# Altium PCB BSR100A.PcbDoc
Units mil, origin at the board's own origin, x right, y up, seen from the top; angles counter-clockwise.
Board outline 2168.5 x 1988.5 mil, 2 copper layers (Top Layer, Bottom Layer), stack 61.2 mil thick; 46 components, 9 nets, 68 pads, 112 vias.
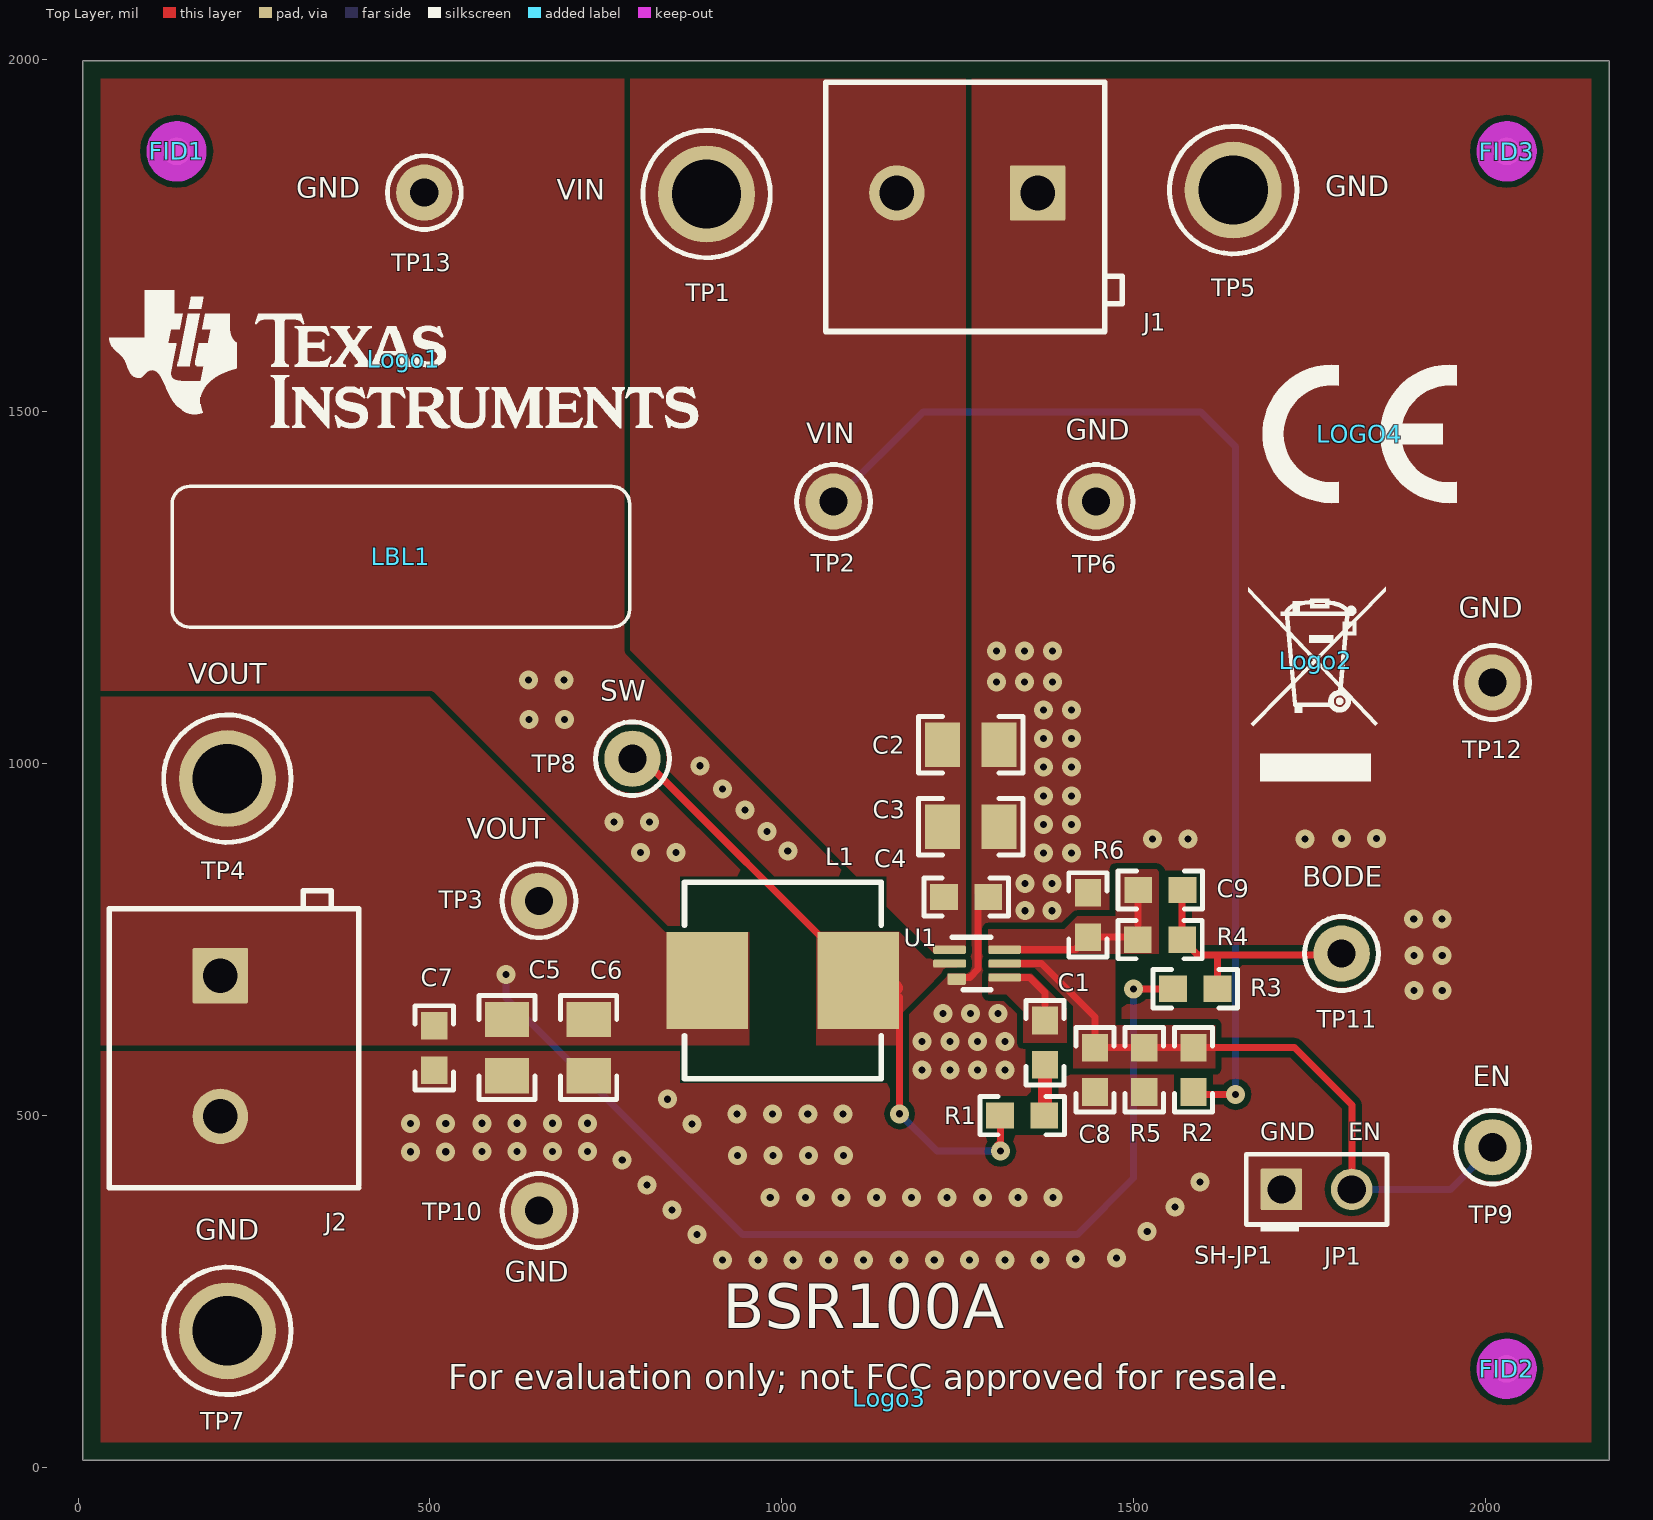
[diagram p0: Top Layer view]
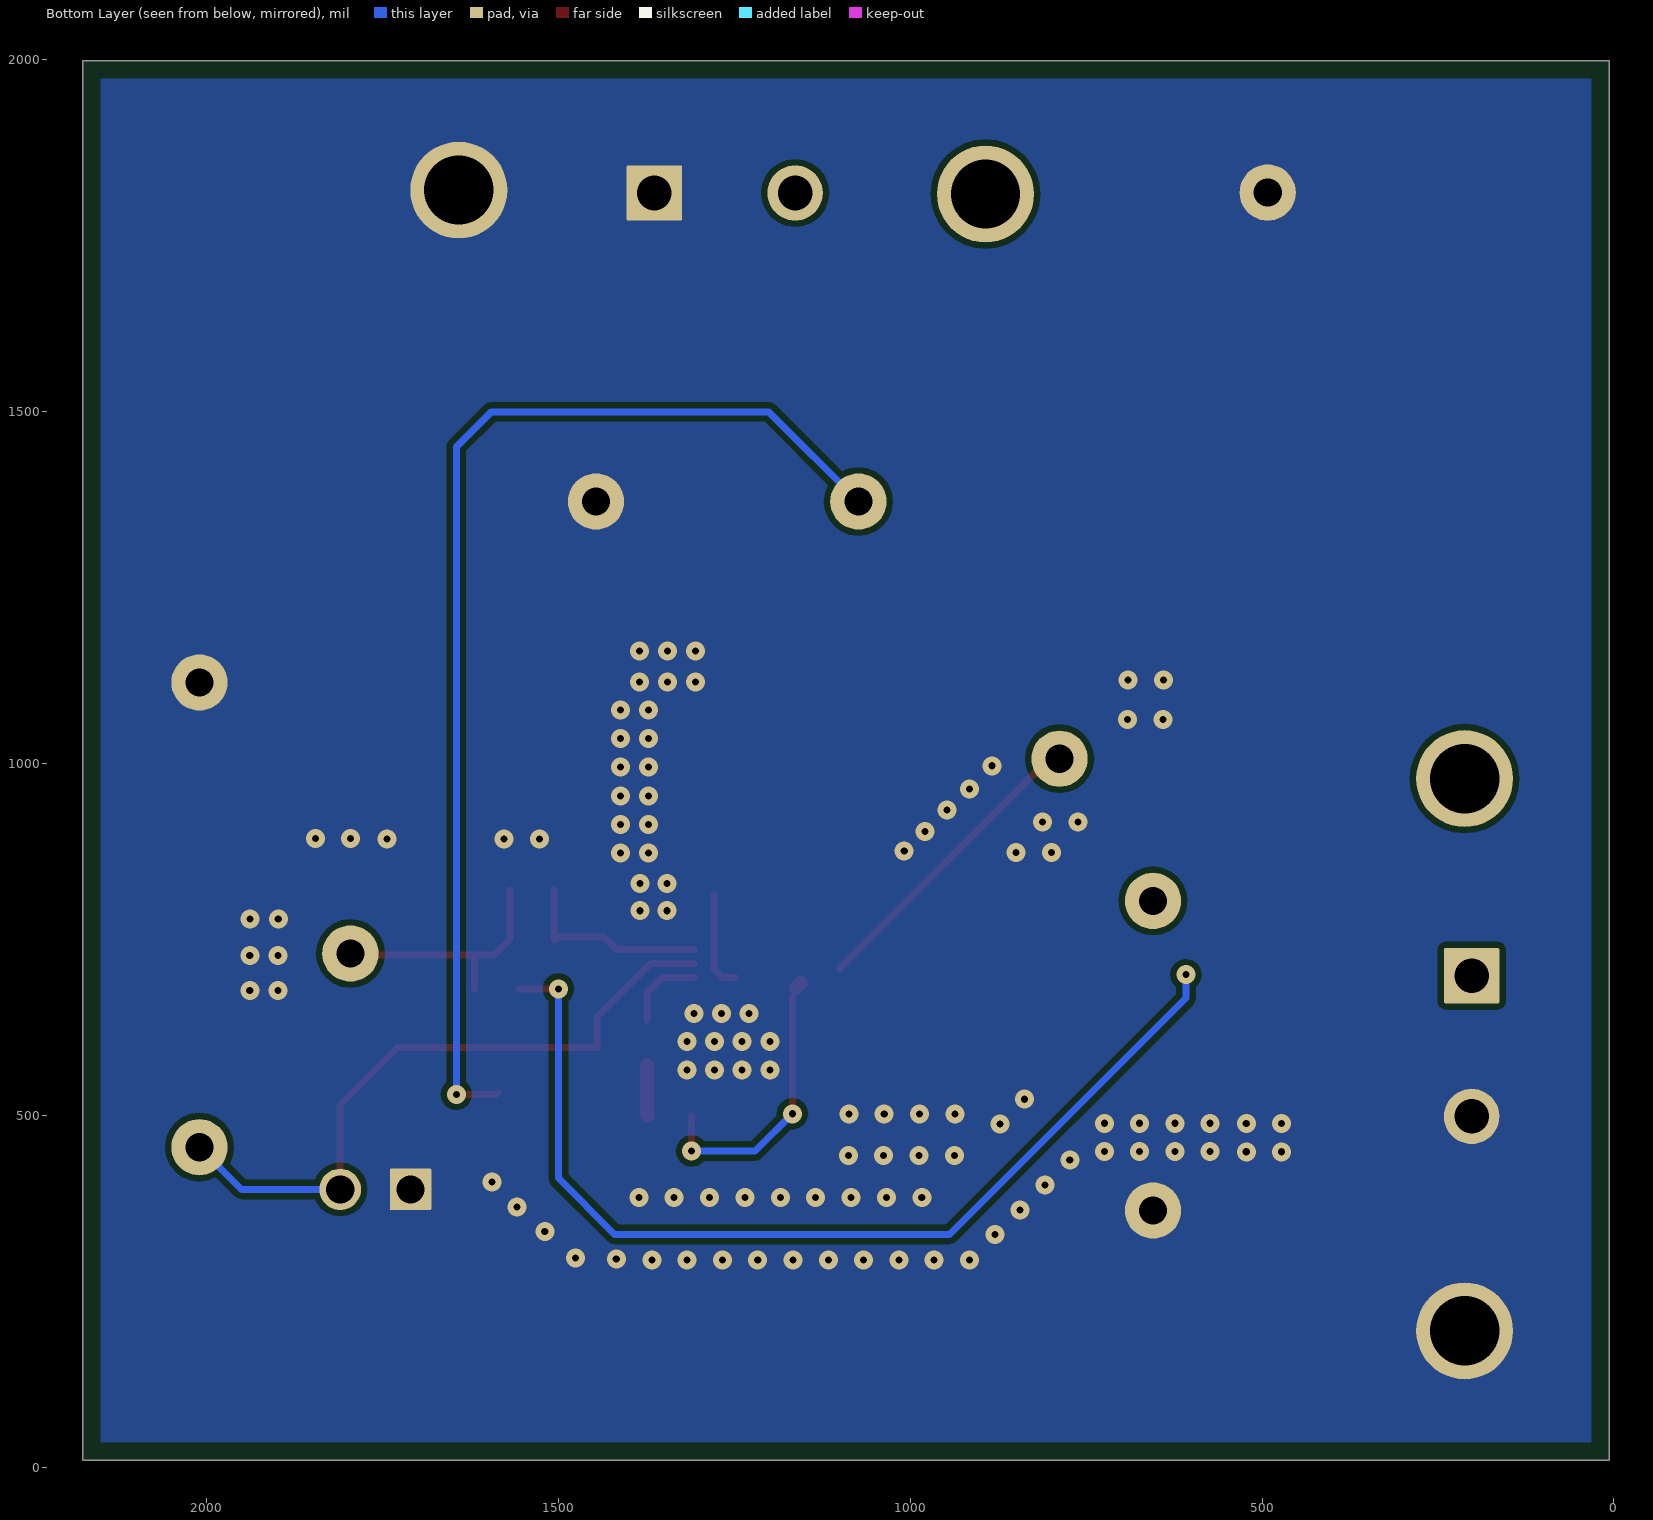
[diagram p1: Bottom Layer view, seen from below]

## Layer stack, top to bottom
Top Solder: solder mask 0.4, Solder Resist, Dk 3.5
Top Layer: signal copper 2.8
Dielectric1: core 55.6, FR-4 High Tg, Dk 4.8
Bottom Layer: signal copper 2.8
Bottom Solder: solder mask 0.4, Solder Resist, Dk 3.5

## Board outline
7,10 2175.5,10 2175.5,1998.5 7,1998.5

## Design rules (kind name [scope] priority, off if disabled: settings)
AcuteAngle [All] p1: minimum=4.50000000000000E+0001 checktracksonly=FALSE
AssemblyTestPointUsage [All] p1: valid=2
BoardOutlineClearance BoardOutlineClearance_MountingHoles [OnCopper and InComponentClass('Mounting Holes')] p1: gap=40 ignorepadtopadclearanceinfootprint=FALSE
BoardOutlineClearance BoardOutlineClearance_Poly [OnCopper and IsPoly] p2: gap=25 ignorepadtopadclearanceinfootprint=FALSE
BoardOutlineClearance [OnCopper and Not InComponentClass('Logo') and not InComponentClass('FiducialMark') and not InRegion(1000,500,4000,800) and not InPoly] p3: gap=75 ignorepadtopadclearanceinfootprint=FALSE
Clearance Clearance_Keepouts [((IsTrack Or IsArc) And Not InPoly) And IsFree and IsKeepOut vs ((IsTrack Or IsArc) And Not InPoly) And IsFree and IsKeepOut] p1: gap=0 ignorepadtopadclearanceinfootprint=FALSE
Clearance Clearance_Poly [InPolygon] p2: gap=8.5 ignorepadtopadclearanceinfootprint=FALSE except(0: Arc-Hole Track-Hole SMDPad-Hole THPad-Hole Via-Hole Fill-Hole Poly-Hole Region-Hole Text-Hole)
Clearance [All] p3: gap=7 ignorepadtopadclearanceinfootprint=FALSE except(0: Arc-Hole Track-Hole SMDPad-Hole THPad-Hole Via-Hole Fill-Hole Poly-Hole Region-Hole Text-Hole)
ComponentClearance ComponentClearance_MountingHoles_FiducialMarks [InComponentClass('Mounting Holes') vs InComponentClass('FiducialMark')] p1: gap=50 collisioncheckmode=3 verticalgap=10 showdistances=FALSE
ComponentClearance ComponentClearance_Shunt [InComponentClass('Header') vs InComponentClass('Shunt')] p2: gap=0 collisioncheckmode=3 verticalgap=0 showdistances=FALSE
ComponentClearance ComponentClearance_Logo [InComponentClass('Logo')] p3: gap=50 collisioncheckmode=3 verticalgap=10 showdistances=FALSE
ComponentClearance ComponentClearance_ScrewToNut [(HasFootprint('NY PMS 440 0025 PH')) vs (HasFootprint('Keystone_1902C'))] p4: gap=5 collisioncheckmode=3 verticalgap=10 showdistances=FALSE
ComponentClearance ComponentClearance_MountingHoles [InComponentClass('Mounting Holes')] p5: gap=250 collisioncheckmode=3 verticalgap=100000 showdistances=FALSE
ComponentClearance ComponentClearance_SmallPassives [HasFootprint('0201*') or HasFootprint('0402*') or HasFootprint('0508') or HasFootprint('0603*') or HasFootprint('0612') or HasFootprint('0805*') or HasFootprint('0815*') or HasFootprint('0830*') or HasFootprint('1206*') or HasFootprint('1210*') or HasFootprint('1808*') or HasFootprint('1812*') or HasFootprint('1825*') or HasFootprint('2010*') or HasFootprint('2220*') or HasFootprint('2225*') or HasFootprint('2512*') or HasFootprint('2728*') or HasFootprint('3518*') vs HasFootprint('0201*') or HasFootprint('0402*') or HasFootprint('0508') or HasFootprint('0603*') or HasFootprint('0612') or HasFootprint('0805*') or HasFootprint('0815*') or HasFootprint('0830*') or HasFootprint('1206*') or HasFootprint('1210*') or HasFootprint('1808*') or HasFootprint('1812*') or HasFootprint('1825*') or HasFootprint('2010*') or HasFootprint('2220*') or HasFootprint('2225*') or HasFootprint('2512*') or HasFootprint('2728*') or HasFootprint('3518*')] p6: gap=14.96 collisioncheckmode=3 verticalgap=10 showdistances=FALSE
ComponentClearance ComponentClearance_THtoSMT [IsThruComponent vs IsSMTComponent] p7: gap=40 collisioncheckmode=3 verticalgap=30 showdistances=FALSE
ComponentClearance ComponentClearance_THtoTH [IsThruComponent vs IsThruComponent] p8: gap=30 collisioncheckmode=3 verticalgap=30 showdistances=FALSE
ComponentClearance [All] p9: gap=30 collisioncheckmode=3 verticalgap=10 showdistances=FALSE
DiffPairsRouting [All] p1: maxlimit=100 minlimit=10 mostfreqgap=10 toplayer_minwidth=15 toplayer_maxwidth=15 toplayer_prefwidth=15 bottomlayer_minwidth=15 bottomlayer_maxwidth=15 bottomlayer_prefwidth=15 maxuncoupledlength=1000
FabricationTestPointUsage TestPointUsage [All] p1: valid=2 allowmultiple=FALSE
FabricationTestpoint Testpoint [All] p1: side=3 testpointundercomponent=TRUE minsize=40 maxsize=100 preferedsize=60 minholesize=0 maxholesize=40 preferedholesize=32 testpointgrid=1 allowsidetop=TRUE allowsidebottom=TRUE usegrid=TRUE gridtolerance=0.01
FanoutControl Fanout_LCC [IsLCC] p1: bgadir=Out bgaviamode=Centered fanoutstyle=Auto fanoutdirection=Alternating viagrid=1 // Fanout_LCC (Default Rule)
FanoutControl Fanout_BGA [IsBGA] p2: bgadir=Out bgaviamode=Centered fanoutstyle=Auto fanoutdirection=Alternating viagrid=1 // Fanout_BGA (Default Rule)
FanoutControl Fanout_Default [All] p4: bgadir=Out bgaviamode=Centered fanoutstyle=Auto fanoutdirection=Alternating viagrid=1 // Fanout_Default (Default Rule)
FanoutControl Fanout_Small [(CompPinCount < 5)] p5: bgadir=Out bgaviamode=Centered fanoutstyle=Auto fanoutdirection=OutThenIn viagrid=1 // Fanout_Small (Default Rule)
HoleSize [All] p1: absolutevalues=TRUE maxlimit=251 minlimit=7.87 maxpercent=80.000 minpercent=20.000
MinimumAnnularRing MinimumAnnularRing_ThermalPadVias [IsVia and InAnyComponent] p1: minimumring=5.91
MinimumAnnularRing [All] p2: minimumring=6
MinimumSolderMaskSliver MinimumSolderMaskSliver_Logo [InComponentClass('Logo') vs InComponentClass('Logo')] p1: minsoldermaskwidth=0.7
MinimumSolderMaskSliver [All] p2: minsoldermaskwidth=3.94
PlaneClearance [All] p1: clearance=0
PlaneConnect [All] p1: planeconnectstyle=Direct reliefexpansion=10 reliefentries=2 reliefconductorwidth=10 reliefairgap=10
PolygonConnect [All] p1: connectstyle=Direct reliefconductorwidth=10 reliefentries=4 polygonreliefangle="90 Angle" airgapwidth=10
RoutingVias ThermalPadVias [IsVia and InAnyComponent] p1: holewidth=7.87 width=19.68 viastyle="Through Hole" minholewidth=7.87 minwidth=19.68 maxholewidth=12.99 maxwidth=23.62
RoutingVias [All] p2: holewidth=16 width=34 viastyle="Through Hole" minholewidth=7.87 minwidth=26 maxholewidth=40 maxwidth=65
SilkToBoardRegionClearance [Not ((IsComment or IsDesignator) And (Hide <> 'False')) and not InRegion(1000,500,4000,800)] p1:
SilkToSilkClearance SilkToSilkClearance_Pb-FreeLogo [(HasFootprint('Pb-Free_Overlay_Medium') OR HasFootprint('Pb-Free_Overlay_Small')) vs (HasFootprint('Pb-Free_Overlay_Medium') OR HasFootprint('Pb-Free_Overlay_Small'))] p1: silktosilkclearance=0
SilkToSilkClearance [All] p2: silktosilkclearance=4
SilkToSolderMaskClearance SilkToComponentPadClearance [(IsPad or IsFill or IsRegion) and InAnycomponent] p1: minsilkscreentomaskgap=2 clearancetoexposedcopper=TRUE
SilkToSolderMaskClearance "Silk to Solder Mask Opening" [All] p2: minsilkscreentomaskgap=0.5 clearancetoexposedcopper=TRUE
SolderMaskExpansion [All] p1: expansion=1.85
Width [All] p1: maxlimit=100 minlimit=3 preferedwidth=10 bottomlayer_minwidth=6 minimp=50.000000 maximp=50.000000 favimp=50.000000 checkconnectedcopper=TRUE
14 further rules are at their usual default settings.

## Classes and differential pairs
component class Label: LBL1
component class Shunt: SH-JP1
component class FiducialMark: FID1 FID2 FID3
component class BSR100A_Hardware: FID1 FID2 FID3 LBL1 Logo1 Logo2 Logo3 LOGO4 LOGO7 SH-JP1 ZZ1 ZZ2 ZZ3 ZZ4
component class Logo: Logo1
component class Header: JP1
component class BSR100A: C1 C2 C3 C4 C5 C6 C7 C8 C9 GND GND3 J1 J2 JP1 L1 R1 R2 R3 R4 R5 R6 TP1 TP2 TP3 TP4 TP5 TP6 TP7 TP8 TP9 TP10 TP11 TP12 TP13 U1 VIN1 VOUT0
component class AssemblyNote: ZZ1 ZZ2 ZZ3 ZZ4

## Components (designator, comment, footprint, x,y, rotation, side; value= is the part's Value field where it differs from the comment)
C1 "C1608X7R1E104K080AA" 0603 1374,603.5 r270 top value=0.1uF
C2 "GRM21BR61E106MA73L" 0805_HV 1268.5,1027 r0 top value=10uF
C3 "GRM21BR61E106MA73L" 0805_HV 1268.5,910.5 r0 top value=10uF
C4 "C1608X7R1E104K080AA" 0603 1262,810.5 r0 top value=0.1uF
C5 "GRM21BR61A226ME44L" 0805_HV 609.5,596.5 r90 top value=22uF
C6 "GRM21BR61A226ME44L" 0805_HV 725.5,596.5 r90 top value=22uF
C7 "C1608X7R1E104K080AA" 0603 506,596 r270 top value=0.1uF
C8 "C1608X7R1H103K080AA" 0603 1445,565 r270 top value=0.01uF
C9 "GRM1885C2A330JA01D" 0603 1538,820.5 r180 top value=33pF
FID1 "Fiducial" Fiducial10-20 140,1870 r0 top
FID2 "Fiducial" Fiducial10-20 2030,140 r0 top
FID3 "Fiducial" Fiducial10-20 2030,1870 r0 top
J1 "ED120/2DS" On-Shore_ED120_2DS 1263.55,1810.91 r180 top
J2 "ED120/2DS" On-Shore_ED120_2DS 202.15,598.71 r270 top
JP1 "PEC02SAAN" CONN_PEC02SAAN 1760,395 r0 top
L1 "74437349012" WE-LHMI_7050 1001.5,692 r180 top value=1.2uH
LBL1 "THT-14-423-10" Label_650x200 458.68,1294 r0 top
Logo1 "Texas Instruments" TI_Stacked_Overlay_Small 463,1574.5 r0 top
Logo2 "WEEE logo" WEEE_Minimum 1758.5,1147 r0 top
Logo3 "FCC disclaimer" FCC_disclaimer 1153,99 r0 top
LOGO4 "CE Mark" CE_Mark_5mm 1821,1468.5 r0 top
R1 "CRCW06030000Z0EA" 0603 1341.5,500 r180 top value=0
R2 "CRCW060320K0JNEA" 0603 1585,565 r270 top value=20k
R3 "CRCW060351R0JNEA" 0603 1587.5,680 r180 top value=51
R4 "RC0603FR-073K09L" 0603 1537.5,750 r180 top value=3.09k
R5 "CRCW060310K0JNEA" 0603 1515,565 r90 top value=10k
R6 "CRCW060310K0FKEA" 0603 1435,785 r270 top value=10.0k
SH-JP1 "SNT-100-BK-G" SNT-100-BK-G 1656,400.5 r180 top value=1x2
TP1 "1502-2" Keystone1502-2 893.05,1809.41 r0 top
TP2 "5000" Keystone5000 1073.64,1372.46 r90 top
TP3 "5000" Keystone5000 655,805 r0 top
TP4 "1502-2" Keystone1502-2 212.15,978.71 r0 top
TP5 "1502-2" Keystone1502-2 1641.5,1815 r0 top
TP6 "5001" Keystone5001 1446.5,1372.46 r90 top
TP7 "1502-2" Keystone1502-2 212.15,194 r0 top
TP8 "5000" Keystone5000 787.75,1007 r90 top
TP9 "5000" Keystone5000 2010,455 r0 top
TP10 "5001" Keystone5001 655,365 r0 top
TP11 "5000" Keystone5000 1795.5,730.2 r0 top
TP12 "5001" Keystone5001 2010,1115.32 r0 top
TP13 "5001" Keystone5001 492,1811.5 r90 top
U1 "TPS563202DRLR" DRL0006A 1277.55,715.91 r0 top
ZZ1 "This Assembly Note is for PCB labels only" AssemblyNoteLabel 3692.5,766.5 r0 top
ZZ2 "These assemblies are ESD sensitive, ESD precautions shall be observed." AssemblyNote 3694.5,622 r0 top
ZZ3 "These assemblies must be clean and free from flux and all contaminants. Use of no clean flux is not acceptable." AssemblyNote 3694.5,498.5 r0 top
ZZ4 "These assemblies must comply with workmanship standards IPC-A-610 Class 2., unless otherwise specified." AssemblyNote 3694.5,366 r0 top

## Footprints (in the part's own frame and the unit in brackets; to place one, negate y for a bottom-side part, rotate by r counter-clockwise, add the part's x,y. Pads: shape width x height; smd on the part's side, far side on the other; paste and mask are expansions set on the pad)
0603 [mm] "0603 from SM-752 data"
  rect 1x0.95 smd: 1(-0.8,0) 2(0.8,0)
  silkscreen extent -1.52,-0.69 1.52,0.69, body extent -0.87,-0.47 0.87,0.47, height 1
0805_HV [mil] "0805 with 30mil clearance between pads"
  rect 50x63 smd: 1(-40,0) 2(40,0)
  silkscreen extent -74,-40 74,40, body extent -43,-29 43,29, height 57
AssemblyNote [mil] "Assembly Note"
AssemblyNoteLabel [mil] "Assembly Note for PCB Labels"
CE_Mark_5mm [mil] "Minimum text height for CE Mark"
  silkscreen extent -138,-98 138,98
CONN_PEC02SAAN [mm] "SULLINS"
  rrect7% 1.5x1.5 hole 1.016: 1(-1.27,0)
  round 1.5 hole 1.016: 2(1.27,0)
  silkscreen extent -2.54,-1.52 2.54,1.27, body extent -2.54,-1.27 2.54,1.27, height 8.38
DRL0006A [mm] "SOTFL, 6-Flat Leads, Body 1.2x1.6x0.6mm, Pitch 0.5mm, TI recommended"
  rrect33% 0.67x0.3 smd: 1(-0.74,0.5) 2(-0.74,0) 3(-0.74,-0.5) 4(0.74,-0.5) 5(0.74,0) 6(0.74,0.5)
  silkscreen extent -0.9,-0.95 0.5,0.95, body extent -0.8,-0.8 0.8,0.8, height 0.61
FCC_disclaimer [mil]
Fiducial10-20 [mm]
  round 1 smd mask+0.5: 1(0,0)
  Top Layer keep-out circle w1.178: c0,0 r0.5
Keystone1502-2 [mm] "Double Turret"
  round 3.5 hole 2.5: 1(0,0)
  silkscreen extent -2.3,-2.3 2.3,2.3, body extent -1.6,-1.6 1.59,1.6, height 5.62
Keystone5000 [mil] "For Keystone 500x miniature loop terminals"
  round 80 hole 40: 1(0,0)
  silkscreen extent -52,-52 52,52, body extent -49,-49 49,49, height 182
Keystone5001 [mil] "For Keystone 500x miniature loop terminals"
  round 80 hole 40: 1(0,0)
  silkscreen extent -52,-52 52,52, body extent -49,-49 49,49, height 182
Label_650x200 [mil] "Thermal Transfer Label"
  round 1 on Mech13: 0(0,0)
  silkscreen extent -325,-100 325,100, body extent -325,-100 325,100, height 1
On-Shore_ED120_2DS [mm] "ONSHORE"
  rrect5% 2x2 hole 1.25: 1(-2.54,0)
  round 2 hole 1.25: 2(2.54,0)
  silkscreen extent -5.6,-4 5.12,5, body extent -5.78,-4 5.08,5, height 13
SNT-100-BK-G [mil] "Samtec STEP model"
  round 1 on Mech3: 0(0,0)
  body extent -100,-50 100,50, height 344
TI_Stacked_Overlay_Small [mil]
  silkscreen extent -418,-98 418,98
WE-LHMI_7050 [mm] "Wurth"
  rect 2.95x3.5 smd: 1(-2.725,0) 2(2.725,0)
  silkscreen extent -3.55,-3.55 3.55,3.55, body extent -3.8,-3.45 3.8,3.45, height 5
WEEE_Minimum [mil] "WEEElie bin"
  silkscreen extent -95,-172 99,104

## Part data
C1 C4 C7: library part CMP-0007039-5, "CAP, CERM, 0.1 uF, 25 V, +/- 10%, X7R, 0603", Cap_Case=0603, Manufacturer=TDK, Supplier Part Number 1=445-1316-1-ND, TempCo=X7R, Tolerance_%=10%, Value1=Unknown, Value2=25V, ValueDisplayed=0.1uF
C2 C3: library part CMP-0008303-3, "CAP, CERM, 10 uF, 25 V, +/- 20%, X5R, 0805", Cap_Case=0805, Manufacturer=MuRata, TempCo=X5R, Tolerance_%=20%, Value1=Unknown, Value2=25V, ValueDisplayed=10uF
C5 C6: library part CMP-0008286-2, "CAP, CERM, 22 uF, 10 V, +/- 20%, X5R, 0805", Cap_Case=0805, Manufacturer=MuRata, Supplier Part Number 1=490-10746-1-ND, TempCo=X5R, Tolerance_%=20%, Value1=Unknown, Value2=10V, ValueDisplayed=22uF
C8: library part CMP-0007043-4, "CAP, CERM, 0.01 uF, 50 V, +/- 10%, X7R, 0603", Cap_Case=0603, Manufacturer=TDK, Supplier Part Number 1=445-1311-1-ND, TempCo=X7R, Tolerance_%=10%, Value1="0.0539 ohm", Value2=50V, ValueDisplayed=0.01uF
C9: library part CMP-0007263-4, "CAP, CERM, 33 pF, 100 V, +/- 5%, C0G/NP0, 0603", Cap_Case=0603, Manufacturer=MuRata, Supplier Part Number 1=490-1339-1-ND, TempCo=C0G/NP0, Tolerance_%=5%, Value1=Unknown, Value2=100V, ValueDisplayed=33pF
FID1 FID2 FID3: library part CMP-0077181-1, "Fiducial mark.  There is nothing to buy or mount.", Manufacturer=N/A
J1 J2: library part CMP-0074910-1, "Terminal Block, 5.08 mm, 2x1, Brass, TH", Color=Blue, Current_A=15A, Manufacturer="On-Shore Technology", Supplier Part Number 1=ED1609-ND, Voltage_V=300V
JP1: library part CMP-0002337-1, "Header, 100mil, 2x1, Tin, TH", Color=Black, Current_A=3A, Manufacturer="Sullins Connector Solutions", Supplier Part Number 1=S1012E-02-ND, Voltage_V=1.8kV
L1: library part CMP-0064104-1, "Inductor, Shielded Drum Core, Powdered Iron, 1.2 uH, 9 A, 0.0072 ohm, SMD", Manufacturer="Wurth Elektronik", Supplier Part Number 1=732-3350-1-ND, Value1="0.0072 ohm", Value2=9A, ValueDisplayed=1.2uH
LBL1: library part CMP-0003625-1, "Thermal Transfer Printable Labels, 0.650\" W x 0.200\" H - 10,000 per roll", Manufacturer=Brady, Supplier Part Number 1=97C5133
Logo1: library part CMP-0074838-1, "Texas Instrument Corporate Signature"
Logo2: library part CMP-0074769-1
Logo3: library part CMP-0074847-1, "FCC_disclaimer"
LOGO4: library part CMP-0074844-1
R1: library part CMP-0025697-4, "RES, 0, 5%, 0.1 W, AEC-Q200 Grade 0, 0603", Manufacturer=Vishay-Dale, Power_W=100mW, Supplier Part Number 1=541-0.0GCT-ND, TempCo="200 ppm/C", Tolerance_%=5%, Value2=0.1W, Value_Code=0000, ValueDisplayed=0
R2: library part CMP-0025753-4, "RES, 20 k, 5%, 0.1 W, AEC-Q200 Grade 0, 0603", Manufacturer=Vishay-Dale, Power_W=100mW, Supplier Part Number 1=541-20KGCT-ND, TempCo="200 ppm/C", Tolerance_%=5%, Value2=0.1W, Value_Code=20k0, ValueDisplayed=20k
R3: library part CMP-0025825-4, "RES, 51, 5%, 0.1 W, AEC-Q200 Grade 0, 0603", Manufacturer=Vishay-Dale, Power_W=100mW, Supplier Part Number 1=541-51GCT-ND, TempCo="200 ppm/C", Tolerance_%=5%, Value2=0.1W, Value_Code=51R0, ValueDisplayed=51
R4: library part CMP-0023077-5, "RES, 3.09 k, 1%, 0.1 W, 0603", Manufacturer=Yageo, Power_W=100mW, Supplier Part Number 1=311-3.09KHRCT-ND, TempCo="100 ppm/C", Tolerance_%=1%, Value2=0.1W, Value_Code=3k09, ValueDisplayed=3.09k
R5: library part CMP-0025701-4, "RES, 10 k, 5%, 0.1 W, AEC-Q200 Grade 0, 0603", Manufacturer=Vishay-Dale, Power_W=100mW, Supplier Part Number 1=541-10KGCT-ND, TempCo="200 ppm/C", Tolerance_%=5%, Value2=0.1W, Value_Code=10k0, ValueDisplayed=10k
R6: library part CMP-0021998-4, "RES, 10.0 k, 1%, 0.1 W, AEC-Q200 Grade 0, 0603", Manufacturer=Vishay-Dale, Power_W=100mW, Supplier Part Number 1=541-10.0KHCT-ND, TempCo="100 ppm/C", Tolerance_%=1%, Value2=0.1W, Value_Code=10k0, ValueDisplayed=10.0k
SH-JP1: library part CMP-0003623-3, "Shunt, 100mil, Gold plated, Black", Alternate Manufacturer=3M, Alternate PartNumber=969102-0000-DA, Manufacturer=Samtec, Supplier Part Number 1=SAM8858-ND
TP1 TP4 TP5 TP7: library part CMP-0055113-1, "Terminal, Turret, TH, Double", Manufacturer=Keystone, Supplier Part Number 1=36-1502-2-ND
TP2 TP3 TP8 TP9 TP11: library part CMP-0055137-1, "Test Point, Miniature, Red, TH", Color=Red, Manufacturer=Keystone, Supplier Part Number 1=36-5000-ND
TP6 TP10 TP12 TP13: library part CMP-0055138-1, "Test Point, Miniature, Black, TH", Color=Black, Manufacturer=Keystone, Supplier Part Number 1=36-5001-ND
U1: library part CMP-0860517-1, "4.5-V to 17-V Input, 3-A Synchronous Buck Converter, DRL0006A (SOT-5X3-6)", Alternate Manufacturer="Texas Instruments", Alternate PartNumber=TPS563202DRLT
ZZ1: library part CMP-0003616-3
ZZ2: library part CMP-0077236-1
ZZ3: library part CMP-0077237-1
ZZ4: library part AssemblyNote

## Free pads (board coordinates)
  rrect33% 26.38x11.81 smd: 3(1228.41,715.91) 3(1228.41,735.59) 3(1248.41,691.71) 3(1326.68,696.22) 3(1326.68,715.91) 3(1326.68,735.59)

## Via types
v1: diameter 27, hole 10, Top Layer to Bottom Layer, 112 vias

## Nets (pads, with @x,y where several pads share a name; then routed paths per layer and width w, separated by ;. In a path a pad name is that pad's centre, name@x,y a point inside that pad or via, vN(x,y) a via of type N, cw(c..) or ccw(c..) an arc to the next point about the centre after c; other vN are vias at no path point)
BST: C1.1 pad.3@1326.68,696.22 U1.4 | length 115.8
  Top Layer w10: U1.4 1326.68,696.22 1352.28,696.22 1374,674.5 C1.1
EN: C8.1 JP1.2 pad.3@1326.68,715.91 R2.1 R5.2 TP9.1 U1.5 | length 956.9
  Top Layer w10: U1.5 1369.09,715.91 1445,640 C8.1 R5.2 R2.1 1728.5,596.5 1810,515 JP1.2
  Bottom Layer w10: JP1.2 1950,395 TP9.1
FB: C9.2 pad.3@1326.68,735.59 R4.2 R6.2 U1.6 | length 276.4
  Top Layer w10: U1.6 1417.09,735.6 R6.2 1500,753.5 R4.2@1503.5,750 ; R4.2 1506.01,820 C9.2
GND: C2.2 C3.2 C4.2 C5.1 C6.1 C7.2 C8.2 J1.1 J2.2 JP1.1 pad.3@1248.41,691.71 R5.1 R6.1 TP5.1 TP6.1 TP7.1 TP10.1 TP12.1 TP13.1 U1.3 | length 140.5
  Top Layer w10: U1.3 1267.23,696.23 1279,708 C4.2@1279,813
  other v1: 916,294.5 966.11,294.5 1016.22,294.5 1066.33,294.5 1116.44,294.5 1166.56,294.5 1216.67,294.5 1266.78,294.5 1316.89,294.5 1367,294.5 1417.7,295.85 1475.7,297.7 879.36,330.64 1519.3,335 844,366 1558.96,370.01 983.61,383.5 1033.86,383.5 1084.11,383.5 1134.36,383.5 1184.61,383.5 1234.86,383.5 1285.11,383.5 1335.36,383.5 1385.61,383.5 808.64,401.36 1594.31,405.36 773.29,436.71 937.25,443 987.5,443 1037.75,443 1088,443 472.5,448.5 522.5,448.5 574,449 624,449 674,449 724,449 472.5,488.5 522.5,488.5 872.71,487.79 574,489 624,489 674,489 724,489 936.4,502.29 986.65,502.29 1036.9,502.29 1087.15,502.29 837.36,523.14 1199.5,565 1238.83,565 1278.17,565 1317.5,565 1199.5,605 1238.83,605 1278.17,605 1317.5,605 1228.83,645 1268.17,645 1307.5,645 1898.5,677.5 1938.5,677.5 1898.5,727.5 1938.5,727.5 1898,779 1938,779 1345.5,791 1384,791 1345.5,830 1384,830 1371.91,873 1412,873 799.25,873.5 849.5,873.5 1008.5,876 1527,893 1577,893 1743.61,893.04 1795.11,893.54 1845.11,893.54 979,903.5 1371.91,913.64 1412,913.64 761.71,917 811.96,917 947.5,934 1371.91,954.28 1412,954.28 916,964 1371.91,994.92 1412,994.92 883.5,997 1371.91,1035.56 1412,1035.56 640.71,1063 690.96,1063 1371.91,1076.2 1412,1076.2 1305,1115.9 1345,1115.9 1385,1116 640.21,1119 690.46,1119 1305,1159.9 1345,1159.9 1385,1159.9
NetC1_2: C1.2 R1.1 | length 72.4
  Top Layer w20: R1.1 1374,501.01 C1.2
NetC9_1: C9.1 R3.1 R4.1 TP11.1 | length 355.2
  Top Layer w10: C9.1 1569,820 R4.1 1590.99,728.01 1619,728.01 ; R3.1 1619,728.01 ; TP11.1 1793.31,728.01 1619,728.01
SW: L1.1 pad.3@1228.41,715.91 R1.2 TP8.1 U1.2 | length 829.1
  Top Layer w10: TP8.1 802.5,1007 1100,709.5 L1.1@1100,707.94 ; v1(1167.5,502.5) 1167.5,668.5 ; v1@1310.5,454 R1.2@1310.5,500
  Top Layer w20: L1.1@1155.5,688.5 L1.1@1162.5,681.5 ; v1@1310,454.5 1310.5,454 v1(1310.5,449.5)
  Bottom Layer w10: v1(1167.5,502.5) 1220.5,449.5 v1(1310.5,449.5)
VIN: C2.1 C3.1 C4.1 J1.2 pad.3@1228.41,735.59 R2.2 TP1.1 TP2.1 U1.1 | length 1626.4
  Top Layer w10: R2.2 1588.5,530 v1(1645,530)
  Bottom Layer w10: TP2.1 1201.18,1500 1595,1500 1645,1450 v1(1645,530)
VOUT: C5.2 C6.2 C7.1 J2.1 L1.2 R3.2 TP3.1 TP4.1 | length 1422.4
  Top Layer w10: v1(1500,680) R3.2
  Bottom Layer w10: v1(608.24,700.14) 608.24,666.76 944,331 1420,331 1500,411 v1(1500,680)
pads on no net: FID1.1 FID2.1 FID3.1 LBL1.0 SH-JP1.0

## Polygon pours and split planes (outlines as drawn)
GND on Top Layer "TOP_LAYER_GND_P104" (solid, remove dead copper, pour order 104): -99,2125.5 -86,2112.5 2289,2112.5 2289,-106.5 2284.5,-111 2276,-102.5 -103.5,-102.5
EN on Top Layer "Top Layer-No Net 1" (solid, remove dead copper, pour order 102): 1293.56,721.8 1473.58,721.8 1473.58,628.51 1616,628.49 1616,567 1414.5,567 1414.5,654.95 1359.42,710.02 1293.56,710.02
FB on Top Layer "Top Layer-No Net 1" (solid, remove dead copper, pour order 100): 1293.5,730 1536,730 1536,850 1474.5,850 1474.5,783 1419.5,783 1401.5,765 1293.5,765
BST on Top Layer "Top Layer-No Net 1" (solid, remove dead copper, pour order 98): 1293.5,701.5 1355,701.5 1405,651.5 1405,603.5 1343,603.5 1343,648 1319,672 1293.5,672
SW on Top Layer "TOP_LAYER_SW_P002" (solid, remove dead copper, pour order 2): 1265,722.7 1265,709.45 1234.45,709.45 1205,680 1172,647 1172,600 1049,600 1049,761 1167,761 1205.3,722.7
VIN on Top Layer "TOP_LAYER_VIN_P006" (solid, remove dead copper, pour order 6): 1261.5,730 1216,730 1152.5,793.5 785,1161 785,1998.5 1261.5,1998.5
VOUT on Top Layer "TOP_LAYER_VOUT_P008" (solid, remove dead copper, pour order 8): 954,760.5 954,600 7,600 7,1095 500,1095 834.5,760.5
GND on Bottom Layer "BOTTOM_LAYER_GND_P108" (solid, remove dead copper, pour order 108): -51.5,2073.5 2211,2073.5 2228,2056.5 2228,-42 -17,-42 -51.5,-76.5
no net on Bottom Layer "BOTTOM_LAYER_NONET_P106" (solid, remove dead copper, pour order 106): -47,2116.5

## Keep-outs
Keep-Out Layer:
  text ".Layer_Name" at 577,-858.49 h60

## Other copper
Top Layer:
  pour cut-out: 854.85,840 1149.5,840 1149.5,768 1042,768 1042,594 1149.5,594 1149.5,546 854.86,546 854.85,594 960,594 960,768 854.85,768
  text ".Layer_Name" at 577,-858.49 h60
Bottom Layer:
  text ".Layer_Name" at 577,-858.49 h60

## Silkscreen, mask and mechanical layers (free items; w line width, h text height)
Top Overlay:
  text "GND" at 1772.5,1796 h50
  text "GND" at 310.05,1794.5 h50
  text "VIN" at 680,1791.5 h50
  text "GND" at 1403.5,1450 h50
  text "VIN" at 1035,1445.5 h50
  text "GND" at 1962,1197.5 h50
  text "VOUT" at 156.5,1103.67 h50
  text "SW" at 742,1079.5 h50
  text "VOUT" at 552.5,883.5 h50
  text "BODE" at 1739.5,815.2 h50
  text "EN" at 1982,532 h50
  text "GND" at 1680,465 h25
  text "EN" at 1805,465 h25
  text "GND" at 166.5,313.5 h50
  text "GND" at 606.08,253.5 h50
  text "BSR100A" at 916,177 h108.27
  text ".Layer_Name" at 577,-858.49 h60
Bottom Overlay:
  text ".Layer_Name" at 577,-858.49 h60
Top Paste:
  text ".Layer_Name" at 577,-858.49 h60
Bottom Paste:
  text ".Layer_Name" at 577,-858.49 h60
Top Solder:
  text ".Layer_Name" at 577,-858.49 h60
  text ".Layer_Name" at 577,-858.49 h60
Bottom Solder:
  text ".Layer_Name" at 577,-858.49 h60
Drill Guide:
  text ".Layer_Name" at 577,-858.49 h60
M1 Board Outline:
  the board outline again, w10
  text ".Layer_Name" at 577,-858.49 h60
M2 Board Dimensions:
  rectangle: 125,-400 500,-275
  rectangle: 0,-275 125,-150
  lines w7: 0,-275 1000,-275 ; 125,-400 125,-150 ; 250,-400 250,-150 ; 500,-400 500,-150 ; 750,-400 750,-150 ; 0,-400 0,-150 1000,-150 1000,-400 0,-400
  text ".Layer_Name" at 577,-858.49 h60
M3 3D STEP Top:
  text ".Layer_Name" at 577,-858.49 h60
M4 3D STEP Bottom:
  text ".Layer_Name" at 577,-858.49 h60
M5 Assembly Top:
  lines w10: -292,-930.17 6308,-930.17 ; -292,-726.83 6310,-726.83 ; -292,-523.5 -292,-1133.5 3713,-1133.5 6310,-1133.5 6310,-523.5 -291.5,-523.5 -291.5,-1133.5 1284,-1133.5 ; 2173,-1133.5 2173,-523.5 ; 3440,-726.83 3440,-523.5 ; 4280,-726.83 4280,-523.5 ; 4902,-1140 4902,-937.17
  text "COMPONENTS MARKED 'DNP' SHOULD NOT BE POPULATED." at 1153.5,-318.5 h60
  text "ASSEMBLY VARIANT:" at 1153,-434 h60
  text ".VariantName" at 2189,-434 h60
  text "PCB VIEWED FROM TOP SIDE" at -228.5,-655.67 h60
  text "BOARD #:" at 2248,-655.67 h60
  text ".PRJ_Number" at 2793.5,-655.67 h60
  text "REV:" at 3638,-655.67 h60
  text ".PCB_Rev" at 3929.5,-655.67 h60
  text "SVN REV:" at 4476,-655.67 h60
  text ".VersionControl_RevNumber" at 4982,-655.67 h60
  text "TID #:" at 2248,-859 h60
  text ".TID" at 2793.5,-859 h60
  text "PLOT NAME =" at -228.5,-1064.34 h60
  text ".plot_File_Name" at 577,-1064.34 h60
  text "GENERATED    :" at 2250,-1064.34 h60
  text ".Print_Date" at 3119.5,-1064.34 h60
  text ".Print_Time" at 3848.5,-1064.34 h60
  text "TEXAS INSTRUMENTS" at 5113,-1064.34 h60
M6 Assembly Bottom:
  lines w10: -292.5,-727.33 6309.5,-727.33 ; -290.5,-930.67 6309.5,-930.67 ; 1115.5,-1140.5 1115.5,-937.67 ; 1737.5,-727.33 1737.5,-524 ; 2577.5,-727.33 2577.5,-524 ; 3844.5,-1134 3844.5,-524 ; 4733.5,-1134 6309,-1134 6309,-524 -292.5,-524 -292.5,-1134 2304.5,-1134 6309.5,-1134 6309.5,-524
  text "COMPONENTS MARKED 'DNP' SHOULD NOT BE POPULATED." at 6102,-318 h60
  text ".VariantName" at 5058,-434 h60
  text "ASSEMBLY VARIANT:" at 6097,-434 h60
  text ".VersionControl_RevNumber" at 1035.5,-656.17 h60
  text "SVN REV:" at 1541.5,-656.17 h60
  text ".PCB_Rev" at 2088,-656.17 h60
  text "REV:" at 2379.5,-656.17 h60
  text ".PRJ_Number" at 3224,-656.17 h60
  text "BOARD #:" at 3769.5,-656.17 h60
  text "PCB VIEWED FROM BOTTOM SIDE" at 6246,-656.17 h60
  text ".TID" at 3224,-859.5 h60
  text "TID #:" at 3769.5,-859.5 h60
  text "TEXAS INSTRUMENTS" at 904.5,-1064.84 h60
  text ".Print_Time" at 2169,-1064.84 h60
  text ".Print_Date" at 2898,-1064.84 h60
  text "GENERATED    :" at 3767.5,-1064.84 h60
  text ".plot_File_Name" at 5440.5,-1064.84 h60
  text "PLOT NAME =" at 6246,-1064.84 h60
M9 Title Sheet:
  drawing of 57 lines, arcs and shapes, not listed
  text "1" at 739.84,8036.5 h70
  text "2" at 3235.5,8036.5 h70
  text "3" at 5724.84,8036.5 h70
  text "4" at 8231.51,8036.5 h70
  text "5" at 10730.5,8036.5 h70
  text "6" at 13235.5,8036.5 h70
  text "A" at -416.5,6893.5 h70
  text "A" at 14383.5,6893.5 h70
  text "B" at -416.5,4513.5 h70
  text "B" at 14383.5,4513.5 h70
  text "C" at -416.5,2138.5 h70
  text "C" at 14383.5,2138.5 h70
  text "PROJECT TITLE:" at 11343.5,277.5 h45
  text ".PRJ_Title" at 11393.5,144.17 h70
  text "DESIGNED FOR:" at 11343.5,-23.5 h45
  text ".PRJ_Customer" at 11393.5,-163.5 h70
  text "D" at -416.5,-231.5 h70
  text "D" at 14383.5,-231.5 h70
  text "FILE NAME:" at 11343.5,-323.5 h45
  text ".PCB_File_Name_No_Path" at 11393.5,-443.5 h70
  text "Texas Instruments (TI) and/or its licensors do not warrant the accuracy or completeness of this specification" at 6374,-605.34 h45
  text "ENGINEER:" at 11343.5,-613.5 h45
  text "LAYOUT BY:" at 12848.5,-613.5 h45
  text "or any information contained therein. TI and/or its licensors do not warrant that this design will meet" at 6329.01,-718 h45
  text ".PRJ_Engineer" at 11393.5,-768.49 h70
  text ".PCB_Layout" at 12899,-768.49 h70
  text "the specifications, will be suitable for your application or fit for any particular purpose, or will operate in" at 6329.01,-830.67 h45
  text ".Layer_Name" at 577,-858.49 h60
  text "ALTIUM DESIGNER VERSION:" at 12848.5,-923.5 h45
  text "an implementation. TI and/or its licensors do not warrant that the design is production worthy. You should" at 6329.01,-943.33 h45
  text "completely validate and test your design implementation to confirm the system functionality for your application." at 6374,-1056 h45
  text ".print_Scale" at 11393.5,-1056.83 h70
  text ".Application_BuildNumber" at 12899,-1056.83 h70
  text "1" at 739.84,-1263.5 h70
  text "2" at 3235.5,-1263.5 h70
  text "3" at 5724.84,-1263.5 h70
  text "4" at 8231.51,-1263.5 h70
  text "5" at 10730.5,-1263.5 h70
  text "6" at 13235.5,-1263.5 h70
M10 Fab Notes:
  drawing of 173 lines, arcs and shapes, not listed
  text "DESIGN INFORMATION" at 12378.02,6201 h60
  text "MIN. TRACK WIDTH:" at 11733.46,6021 h60
  text "8" at 12829.7,6021 h60
  text "MIL" at 12984.46,6021 h60
  text "MIN. CLEARANCE:" at 11733.46,5889 h60
  text "0.2" at 12769.7,5889 h60
  text "mm" at 12984.46,5889 h60
  text "MIN. VIA PAD SIZE:" at 11733.46,5757 h60
  text "24" at 12799.71,5757 h60
  text "MIL" at 12984.46,5757 h60
  text "0.05mm (2MIL)" at 12428.46,5615.29 h60
  text "MINIMUM ANNULAR RING" at 11404.23,5611 h60
  text "EXTERNAL" at 13136.46,5611 h60
  text "PER" at 11604.23,5493 h60
  text "IPC-D-275 CLASS 2 LEVEL C" at 11824.23,5493 h60
  text "MIL, HOLES" at 13312.46,5380.71 h60
  text "+/-" at 12920,5380 h60
  text "+/-" at 13774,5380 h60
  text "REGISTRATION TOLERANCES:" at 11404.23,5375 h60
  text "METAL" at 12604,5375 h60
  text "5" at 13180.2,5375 h60
  text "3" at 14013.2,5375 h60
  text "MIL" at 14129.46,5375 h60
  text "+/-" at 13774,5262 h60
  text "HOLE SIZE TOLERANCE (UNLESS OTHERWISE SPECIFIED):" at 11404.23,5257 h60
  text "3" at 14013.2,5257 h60
  text "MIL" at 14129.46,5257 h60
  text "MATERIAL:" at 11329.46,5047.54 h60
  text "FR-4 High Tg" at 12315.9,4907.21 h60
  text "FR-408" at 11750.46,4898.64 h60
  text "OTHER" at 13238.46,4898.64 h60
  text "X" at 12161,4895 h60
  text "62 MIL (1.6mm) +/-10%" at 12070.56,4735.92 h60
  text "THICKNESS:" at 11404.23,4731.64 h60
  text "X" at 11942.4,4731.64 h60
  text "OTHER" at 13355.46,4731.64 h60
  text "TOLERANCE:" at 11404.23,4573.64 h60
  text "X" at 12243.53,4573.64 h60
  text "ANSI IPC-6012 TYPE 3 CLASS 2" at 12430.48,4573.64 h60
  text "OTHER +/-" at 12430.46,4417.64 h60
  text "BOW & TWIST:" at 11404.23,4260.64 h60
  text "X" at 12243.53,4260.64 h60
  text "ANSI IPC-6012 TYPE 3 CLASS 2" at 12430.48,4260.64 h60
  text "OTHER +/-" at 12430.46,4102.13 h60
  text "DRILLING:" at 11329.46,3963.64 h60
  text "REFERENCE:" at 11404.23,3846.64 h60
  text "X" at 12052.46,3846.64 h60
  text "AS SHOWN" at 12239.46,3846.64 h60
  text "X" at 12953.46,3846.64 h60
  text "NC_DRILL FILES" at 13090.46,3846.64 h60
  text "PTH COPPER THICKNESS:" at 11404.23,3688.64 h60
  text "X" at 12534.46,3688.64 h60
  text "20-30 um" at 12671.46,3688.64 h60
  text "OTHER" at 13388.46,3688.64 h60
  text "BOARD FINISH:" at 11329.46,3529.64 h60
  text "SILKSCREEN:" at 11484.68,3411.64 h60
  text "X" at 12433.46,3411.64 h60
  text "TOP" at 12559.46,3411.64 h60
  text "X" at 12943.46,3411.64 h60
  text "BOTTOM" at 13070.46,3411.64 h60
  text "SILKSCREEN COLOR:" at 11484.68,3244.64 h60
  text "X" at 12432.42,3244.64 h60
  text "WHITE" at 12559.46,3244.64 h60
  text "OTHER" at 13070.46,3244.64 h60
  text "X" at 12563.42,3085.44 h60
  text "GREEN" at 12690.46,3085.44 h60
  text "OTHER" at 13308.46,3085.44 h60
  text "SOLDER RESIST COLOR:" at 11484.68,3074.64 h60
  text "X" at 12563.42,2915.44 h60
  text "MATTE" at 12690.46,2915.44 h60
  text "SEMI-GLOSS" at 13308,2914.8 h60
  text "IMMERSION GOLD (ENIG)" at 12390.46,2726.92 h60
  text "ENEPIG" at 13728,2723.64 h60
  text "SURFACE FINISH:" at 11329.46,2722.64 h60
  text "X" at 12203.51,2722.64 h60
  text "IMM. TIN/SILVER OR EQUIV" at 11659,2565.64 h60
  text "OTHER" at 13090.46,2565.64 h60
  text "ARRAY/PANEL:" at 11329.46,2386.64 h60
  text "CUT AND TRIM PER M1 BOARD OUTLINE" at 12390.46,2382.35 h60
  text "N.C. ROUTE" at 12390.46,2230.64 h60
  text "X" at 13069.46,2230.64 h60
  text "V. SCORE" at 13256.46,2230.64 h60
  text "CERTIFICATION:" at 11329.46,2093.64 h60
  text "MATERIALS AND WORKMANSHIP FOR ALL PCBS" at 12054.46,2093.64 h60
  text "TO MEET OR EXCEED THE REQUIREMENTS OF:" at 12054.46,1995.64 h60
  text "X" at 11680.96,1859.13 h60
  text "ANSI IPC-A-600F CLASS ->" at 11819.96,1859.13 h60
  text "X" at 13459.02,1859.13 h60
  text "2" at 13577.96,1859.14 h60
  text "1" at 13262.96,1857.64 h60
  text "3" at 13931.96,1857.64 h60
  text "X" at 12495.02,1699.64 h60
  text "RoHS" at 12631.96,1699.64 h60
  text "OTHER" at 13276.36,1699.64 h60
  text "PER ORDER" at 13673.42,1699.64 h60
  text "ALL BOARDS MUST MEET OR EXCEED UL94-V0 REQUIREMENTS." at 11357,1534 h60
  text "PCB MUST BEAR THE UL94V-0 UL REGISTERED MATERIAL ID NUMBER" at 11357,1414 h60
  text "ADDITIONAL REQUIREMENTS:" at 11329.46,1240.64 h60
  text "MICROSECTION:" at 11404.23,1125.64 h60
  text "YES" at 12309.96,1125.64 h60
  text "REQUIRED" at 13171.46,969.49 h60
  text "BARE BOARD ELEC. TEST:" at 11404.23,966.64 h60
  text "NONE" at 12709.96,966.64 h60
  text "X" at 13044.46,966.64 h60
  text "PER ORDER" at 13763.46,966.64 h60
  text ".Layer_Name" at 577,-858.49 h60
M11 Gerber Information:
  lines w10: -292,-930.17 6308,-930.17 ; -292,-726.83 6310,-726.83 ; -292,-523.5 -292,-1133.5 3713,-1133.5 6310,-1133.5 6310,-523.5 -291.5,-523.5 -291.5,-1133.5 1284,-1133.5 ; 2173,-1133.5 2173,-523.5 ; 3440,-726.83 3440,-523.5 ; 4280,-726.83 4280,-523.5 ; 4902,-1140 4902,-937.17
  text "ALL ARTWORK VIEWED FROM TOP SIDE" at -228.5,-655.67 h60
  text "BOARD #:" at 2248,-655.67 h60
  text ".PRJ_Number" at 2793.5,-655.67 h60
  text "REV:" at 3638,-655.67 h60
  text ".PCB_Rev" at 3929.5,-655.67 h60
  text "SVN REV:" at 4476,-655.67 h60
  text ".VersionControl_RevNumber" at 4982,-655.67 h60
  text "LAYER NAME =" at -228.5,-858.49 h60
  text "TID #:" at 2248,-859 h60
  text ".TID" at 2793.5,-859 h60
  text "PLOT NAME =" at -228.5,-1064.34 h60
  text ".plot_File_Name" at 577,-1064.34 h60
  text "GENERATED    :" at 2250,-1064.34 h60
  text ".Print_Date" at 3119.5,-1064.34 h60
  text ".Print_Time" at 3848.5,-1064.34 h60
  text "TEXAS INSTRUMENTS" at 5113,-1064.34 h60
M12 Stackup:
  drawing of 165 lines, arcs and shapes, not listed
  text "Layer" at 3583.09,3450.5 h60
  text "Name" at 3993,3450.5 h60
  text "Material" at 4852.77,3450.5 h60
  text "Thickness" at 5712.53,3450.5 h60
  text "Constant" at 6362.37,3450.5 h60
  text "Board Layer Stack" at 6932.23,3450.5 h60
  text "1" at 3583.09,3330.5 h60
  text "Top Overlay" at 3993,3330.5 h60
  text "2" at 3583.09,3210.5 h60
  text "Top Solder" at 3993,3210.5 h60
  text "Solder Resist" at 4852.77,3210.5 h60
  text "0.40mil" at 5712.53,3210.5 h60
  text "3.5" at 6362.37,3210.5 h60
  text "3" at 3583.09,3090.5 h60
  text "Top Layer" at 3993,3090.5 h60
  text "Copper" at 4852.77,3090.5 h60
  text "2.80mil" at 5712.53,3090.5 h60
  text "4" at 3583.09,2970.5 h60
  text "Dielectric1" at 3993,2970.5 h60
  text "FR-4 High Tg" at 4852.77,2970.5 h60
  text "55.60mil" at 5712.53,2970.5 h60
  text "4.8" at 6362.37,2970.5 h60
  text "5" at 3583.09,2850.5 h60
  text "Bottom Layer" at 3993,2850.5 h60
  text "Copper" at 4852.77,2850.5 h60
  text "2.80mil" at 5712.53,2850.5 h60
  text "6" at 3583.09,2730.5 h60
  text "Bottom Solder" at 3993,2730.5 h60
  text "Solder Resist" at 4852.77,2730.5 h60
  text "0.40mil" at 5712.53,2730.5 h60
  text "3.5" at 6362.37,2730.5 h60
  text ".Layer_Name" at 577,-858.49 h60
M13 Component Bodies Top:
  text ".Layer_Name" at 577,-858.49 h60
M14 Component Bodies Bottom:
  text ".Layer_Name" at 577,-858.49 h60
M15 Courtyards Top:
  text ".Layer_Name" at 577,-858.49 h60
M16 Courtyards Bottom:
  text ".Layer_Name" at 577,-858.49 h60
Drill Drawing:
  lines w10: 4088.64,1572.54 4143.96,1572.54 4143.96,1627.86 4088.64,1627.86 4088.64,1572.54 ; 4088.64,1697 4116.3,1710.83 4143.96,1697 4130.13,1724.66 4143.96,1752.32 4116.3,1738.49 4088.64,1752.32 4102.47,1724.66 4088.64,1697 ; 4088.64,1876.78 4143.96,1876.78 4116.3,1821.46 4088.64,1876.78 ; 4088.64,1973.58 4116.3,1945.92 4143.96,1973.58 4116.3,2001.24 4088.64,1973.58
  lines w12: 4038.5,1535.21 7271.26,1535.21 ; 4038.5,2033.04 7271.26,2033.04 ; 4376.67,1410.75 4376.67,2157.5 ; 4708.78,1410.75 4708.78,2157.5 ; 5345.79,1410.75 5345.79,2157.5 ; 5605.14,1410.75 5605.14,2157.5 ; 5980.56,1410.75 5980.56,2157.5 ; 6704.41,1410.75 6704.41,2157.5 ; 4038.5,1410.75 7271.26,1410.75 7271.26,2157.5 4038.5,2157.5 4038.5,1410.75
  text "Symbol" at 4113.18,2070.38 h72
  text "Quantity" at 4414.01,2070.38 h72
  text "Finished Hole Size" at 4746.12,2070.38 h72
  text "Plated" at 5383.12,2070.38 h72
  text "Hole Type" at 5642.48,2070.38 h72
  text "Drill Layer Pair" at 6017.9,2070.38 h72
  text "Hole Tolerance" at 6741.75,2070.38 h72
  text "112" at 4414.01,1945.92 h60
  text "10.00mil (0.254mm)" at 4746.12,1945.92 h60
  text "PTH" at 5383.12,1945.92 h60
  text "Round" at 5642.48,1945.92 h60
  text "Top Layer - Bottom Layer" at 6017.9,1945.92 h60
  text "11" at 4414.01,1821.46 h60
  text "40.00mil (1.016mm)" at 4746.12,1821.46 h60
  text "PTH" at 5383.12,1821.46 h60
  text "Round" at 5642.48,1821.46 h60
  text "Top Layer - Bottom Layer" at 6017.9,1821.46 h60
  text "4" at 4414.01,1697 h60
  text "49.21mil (1.250mm)" at 4746.12,1697 h60
  text "PTH" at 5383.12,1697 h60
  text "Round" at 5642.48,1697 h60
  text "Top Layer - Bottom Layer" at 6017.9,1697 h60
  text "4" at 4414.01,1572.54 h60
  text "98.43mil (2.500mm)" at 4746.12,1572.54 h60
  text "PTH" at 5383.12,1572.54 h60
  text "Round" at 5642.48,1572.54 h60
  text "Top Layer - Bottom Layer" at 6017.9,1572.54 h60
  text "131 Total" at 4414.01,1448.09 h60
  text ".Layer_Name" at 577,-858.49 h60
M17 Embedded Cavity:
  text ".Layer_Name" at 577,-858.49 h60
M18 Embedded Assembly:
  text ".Layer_Name" at 577,-858.49 h60
M19 Embedded Keepout:
  text ".Layer_Name" at 577,-858.49 h60

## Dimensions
0,0 to 2175.5,10 on M2 Board Dimensions
0,0 to 7,1998.5 on M2 Board Dimensions
0,-400 to 1000,-400 on M2 Board Dimensions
